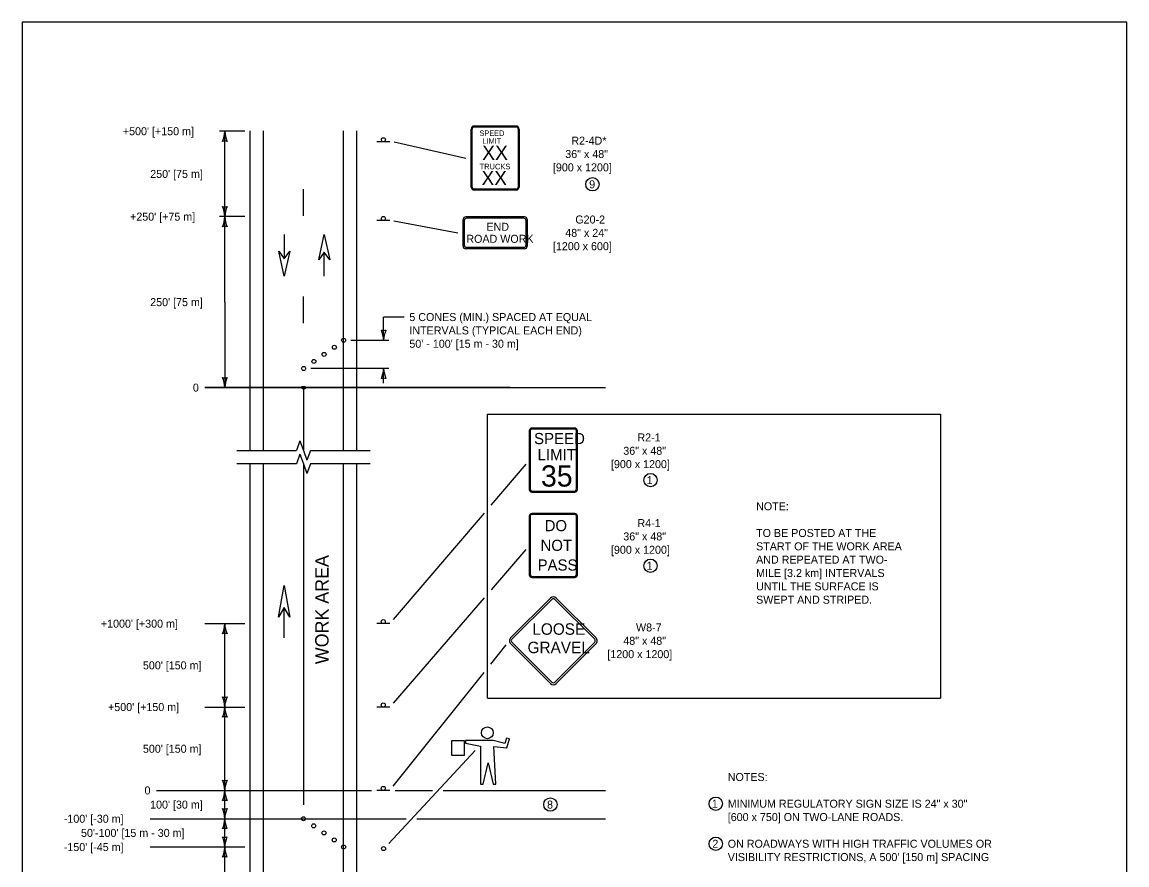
# Model space of a CAD drawing. Extents: x 49991.4 to 50021, y 49987.6 to 50011.4.
# Drawn here: x 50000.34 to 50008.61, y 50004.95 to 50011.26 of the extents above; entities that cross this region are included whole.
import ezdxf

# ---------------------------------------------------------------- set-up
doc = ezdxf.new("R2010")
doc.units = 0
for name, color, linetype in [('Level 1', 7, 'Continuous'), ('Level 2', 7, 'Continuous'), ('Level 3', 7, 'Continuous'), ('Level 6', 7, 'Continuous')]:
    doc.layers.add(name, color=color, linetype=linetype)

msp = doc.modelspace()

# ---------------------------------------------------------------- linework, layer by layer
at = {"layer": 'Level 1'}
for p, q in [((50003.7005, 50010.0267), (50003.7005, 50010.4616)), ((50003.7081, 50010.0267), (50003.7081, 50010.4616)), ((50004.038, 50010.4841), (50003.723, 50010.4841)), ((50004.038, 50010.4765), (50003.723, 50010.4765)), ((50004.0529, 50010.4616), (50004.0529, 50010.0267)), ((50004.0605, 50010.4616), (50004.0605, 50010.0267)), ((50002.0451, 50008.0525), (50002.0451, 50010.4481)), ((50002.1451, 50008.0525), (50002.1451, 50010.4481)), ((50002.745, 50008.0525), (50002.745, 50010.4481)), ((50002.845, 50008.0525), (50002.845, 50010.4481)), ((50003.0909, 50010.3657), (50002.9951, 50010.3657)), ((50003.8841, 50010.2864), (50003.8841, 50010.2864)), ((50002.445, 50009.8103), (50002.445, 50010.0102)), ((50004.038, 50010.0118), (50003.723, 50010.0118)), ((50004.038, 50010.0042), (50003.723, 50010.0042)), ((50004.1005, 50009.8033), (50003.6605, 50009.8033)), ((50003.091, 50009.7754), (50002.9951, 50009.7754)), ((50003.6405, 50009.5833), (50003.6405, 50009.7833)), ((50003.6505, 50009.5883), (50003.6505, 50009.7783)), ((50004.0955, 50009.7933), (50003.6655, 50009.7933)), ((50004.1105, 50009.7783), (50004.1105, 50009.5883)), ((50004.1205, 50009.7833), (50004.1205, 50009.5833)), ((50002.3, 50009.6701), (50002.3, 50009.4891)), ((50002.3003, 50009.6701), (50002.3003, 50009.4891)), ((50004.1004, 50009.5633), (50003.6604, 50009.5633)), ((50004.0955, 50009.5733), (50003.6655, 50009.5733)), ((50002.5997, 50009.3578), (50002.5997, 50009.5384)), ((50002.6, 50009.3578), (50002.6, 50009.5384)), ((50002.445, 50009.007), (50002.445, 50009.2068)), ((50002.4443, 50008.5236), (50002.4443, 50008.0511)), ((50004.1364, 50008.2002), (50004.1364, 50007.7602)), ((50004.1439, 50008.2002), (50004.1439, 50007.7602)), ((50004.4776, 50008.2202), (50004.1551, 50008.2202)), ((50004.4776, 50008.2122), (50004.1551, 50008.2122)), ((50004.4889, 50007.7602), (50004.4889, 50008.2002)), ((50004.4964, 50007.7602), (50004.4964, 50008.2002)), ((50002.0443, 50000.5232), (50002.0443, 50007.9525)), ((50002.1443, 50001.4605), (50002.1443, 50007.9525)), ((50002.4443, 50007.9511), (50002.4443, 50005.3976)), ((50002.7443, 50001.4605), (50002.7443, 50007.9525)), ((50002.8443, 50000.5232), (50002.8443, 50007.9525)), ((50004.1551, 50007.7482), (50004.4776, 50007.7482)), ((50004.1551, 50007.7402), (50004.4776, 50007.7402)), ((50004.4776, 50007.5806), (50004.1551, 50007.5806)), ((50004.4776, 50007.5726), (50004.1551, 50007.5726)), ((50004.1364, 50007.5606), (50004.1364, 50007.1206)), ((50004.1439, 50007.5606), (50004.1439, 50007.1206)), ((50004.4889, 50007.1206), (50004.4889, 50007.5606)), ((50004.4964, 50007.1206), (50004.4964, 50007.5606)), ((50004.1551, 50007.1086), (50004.4776, 50007.1086)), ((50004.1551, 50007.1006), (50004.4776, 50007.1006)), ((50003.9961, 50006.6476), (50004.295, 50006.9464)), ((50004.3051, 50006.9363), (50004.0062, 50006.6375)), ((50004.3051, 50006.9363), (50004.3051, 50006.9363)), ((50004.6264, 50006.6375), (50004.3276, 50006.9363)), ((50004.3377, 50006.9464), (50004.6365, 50006.6476)), ((50002.299, 50006.6496), (50002.299, 50006.8755)), ((50002.2993, 50006.6496), (50002.2993, 50006.8755)), ((50003.0903, 50006.7547), (50002.9943, 50006.7547)), ((50004.295, 50006.306), (50003.9961, 50006.6049)), ((50004.0062, 50006.615), (50004.3051, 50006.3161)), ((50004.3276, 50006.3161), (50004.6264, 50006.615)), ((50004.6365, 50006.6049), (50004.3377, 50006.306)), ((50003.0903, 50006.1297), (50002.9943, 50006.1297)), ((50003.5567, 50005.766), (50003.5567, 50005.8785)), ((50003.5567, 50005.8785), (50003.6486, 50005.8785)), ((50003.6486, 50005.8785), (50003.6486, 50005.766)), ((50003.8658, 50005.8778), (50003.6589, 50005.8778)), ((50003.6589, 50005.8778), (50003.6589, 50005.8592)), ((50003.6589, 50005.8592), (50003.7714, 50005.837)), ((50003.7714, 50005.837), (50003.7714, 50005.5507)), ((50003.9526, 50005.8578), (50003.8658, 50005.8778)), ((50003.8845, 50005.5507), (50003.8697, 50005.8341)), ((50003.8697, 50005.8341), (50003.9673, 50005.8231)), ((50003.9653, 50005.8974), (50003.9526, 50005.8578)), ((50003.9873, 50005.8919), (50003.9653, 50005.8974)), ((50003.9673, 50005.8231), (50003.9873, 50005.8919)), ((50003.6486, 50005.766), (50003.5567, 50005.766)), ((50003.7896, 50005.5507), (50003.8279, 50005.712)), ((50003.8279, 50005.712), (50003.8662, 50005.5507)), ((50003.0903, 50005.5047), (50002.9943, 50005.5047)), ((50003.7714, 50005.5507), (50003.7896, 50005.5507)), ((50003.8662, 50005.5507), (50003.8845, 50005.5507))]:
    msp.add_line(p, q, dxfattribs=at)
for points in [[(50008.6146, 50011.2628), (50000.3356, 50011.2628), (50000.3356, 50000.0624), (50008.6146, 50000.0624)], [(50002.558, 50009.4807), (50002.5997, 50009.6698), (50002.6416, 50009.4807), (50002.5997, 50009.5384)], [(50002.3421, 50009.5472), (50002.3003, 50009.3578), (50002.2585, 50009.5472), (50002.3003, 50009.4893)], [(50002.2573, 50006.8032), (50002.299, 50007.0397), (50002.3409, 50006.8032), (50002.299, 50006.8754)]]:
    msp.add_lwpolyline(points, close=True, dxfattribs=at)
for points in [[(50003.9652, 50005.8972), (50003.9654, 50005.8974)], [(50003.9667, 50005.8232), (50003.9676, 50005.8243)], [(50003.6482, 50005.766), (50003.6486, 50005.7664)]]:
    msp.add_lwpolyline(points, dxfattribs=at)
for centre, radius in [((50003.0429, 50010.3811), 0.0152), ((50003.043, 50009.7908), 0.0152), ((50002.745, 50008.8789), 0.015), ((50002.6755, 50008.8259), 0.015), ((50002.5219, 50008.7198), 0.015), ((50002.5987, 50008.7729), 0.015), ((50002.4451, 50008.6668), 0.015), ((50003.0423, 50006.7701), 0.0152), ((50003.0423, 50006.145), 0.0152), ((50003.8221, 50005.9366), 0.0442), ((50003.0423, 50005.52), 0.0152), ((50002.4442, 50005.2926), 0.015), ((50002.5211, 50005.2396), 0.015), ((50002.5979, 50005.1865), 0.015), ((50002.6747, 50005.1335), 0.015), ((50002.7442, 50005.0805), 0.015), ((50003.0442, 50005.0691), 0.0152)]:
    msp.add_circle(centre, radius, dxfattribs=at)
for centre, radius, start, end in [((50003.723, 50010.4616), 0.0225, 90, 180), ((50003.723, 50010.4616), 0.0149, 90, 180), ((50004.038, 50010.4616), 0.0225, 0, 90), ((50004.038, 50010.4616), 0.0149, 0, 90), ((50003.723, 50010.0267), 0.0225, 180, 270), ((50003.723, 50010.0267), 0.0149, 180, 270), ((50004.038, 50010.0267), 0.0225, 270, 0), ((50004.038, 50010.0267), 0.0149, 270, 0), ((50003.6605, 50009.7833), 0.02, 90, 180), ((50004.1005, 50009.7833), 0.02, 360, 90), ((50003.6655, 50009.7783), 0.015, 90, 180), ((50004.0955, 50009.7783), 0.015, 360, 90), ((50003.6604, 50009.5833), 0.02, 180, 270), ((50003.6655, 50009.5883), 0.015, 180, 270), ((50004.0955, 50009.5883), 0.015, 270, 360), ((50004.1004, 50009.5833), 0.02, 270, 360), ((50004.3164, 50006.925), 0.0302, 45.00008, 134.99993), ((50004.3164, 50006.925), 0.0159, 45.00008, 134.99993), ((50004.0175, 50006.6262), 0.0302, 134.99993, 225.00008), ((50004.0175, 50006.6262), 0.0159, 134.99993, 225.00008), ((50004.6152, 50006.6262), 0.0159, 314.99993, 45.00007), ((50004.6152, 50006.6262), 0.0302, 314.99993, 45.00008), ((50004.3164, 50006.3273), 0.0302, 225.00007, 314.99993), ((50004.3164, 50006.3273), 0.0159, 225.00007, 314.99993)]:
    msp.add_arc(centre, radius, start, end, dxfattribs=at)
msp.add_ellipse((50002.4451, 50008.5236), major_axis=(-0.015, 0), ratio=0.8, dxfattribs=at)
for centre, major_axis, start_param, end_param in [((50004.1552, 50008.2002), (0, 0.02), 0, 1.570796), ((50004.1552, 50008.2002), (0, 0.012), 0, 1.570796), ((50004.4777, 50008.2002), (0, 0.02), 4.712389, 6.283185), ((50004.4777, 50008.2002), (0, 0.012), 4.712389, 6.283185), ((50004.1552, 50007.7602), (0, -0.02), 4.712389, 6.283185), ((50004.1552, 50007.7602), (0, -0.012), 4.712389, 6.283185), ((50004.4777, 50007.7602), (0, -0.02), 0, 1.570796), ((50004.4777, 50007.7602), (0, -0.012), 0, 1.570796), ((50004.1552, 50007.5605), (0, 0.02), 0, 1.570796), ((50004.1552, 50007.5605), (0, 0.012), 0, 1.570796), ((50004.4777, 50007.5605), (0, 0.02), 4.712389, 6.283185), ((50004.4777, 50007.5605), (0, 0.012), 4.712389, 6.283185), ((50004.1552, 50007.1205), (0, -0.02), 4.712389, 6.283185), ((50004.1552, 50007.1205), (0, -0.012), 4.712389, 6.283185), ((50004.4777, 50007.1205), (0, -0.02), 0, 1.570796), ((50004.4777, 50007.1205), (0, -0.012), 0, 1.570796)]:
    msp.add_ellipse(centre, major_axis=major_axis, ratio=0.9375, start_param=start_param, end_param=end_param, dxfattribs=at)
at = {"layer": 'Level 2'}
for p, q in [((50003.8232, 50008.3236), (50007.2172, 50008.3236)), ((50003.8232, 50006.1967), (50003.8232, 50008.3236)), ((50007.2172, 50008.3236), (50007.2172, 50006.1967)), ((50003.8232, 50006.1967), (50007.2172, 50006.1967))]:
    msp.add_line(p, q, dxfattribs=at)
for centre in [(50004.6097, 50010.0473), (50005.0447, 50007.8302), (50005.0445, 50007.1884), (50004.2943, 50005.3987), (50005.5336, 50005.4053), (50005.5336, 50005.1053)]:
    msp.add_circle(centre, 0.05, dxfattribs=at)
at = {"layer": 'Level 3'}
for p, q in [((50002.005, 50010.4452), (50001.8151, 50010.4452)), ((50001.8551, 50009.8047), (50001.8551, 50010.4452)), ((50003.1241, 50010.3657), (50003.6605, 50010.2442)), ((50002.0051, 50009.8047), (50001.8151, 50009.8047)), ((50002.0051, 50009.8047), (50001.8151, 50009.8047)), ((50001.8551, 50009.1641), (50001.8551, 50009.8047)), ((50003.1221, 50009.7727), (50003.6005, 50009.6833)), ((50001.8551, 50009.1641), (50001.8551, 50008.5236)), ((50003.045, 50008.8789), (50003.045, 50009.0523)), ((50003.1976, 50009.0523), (50003.045, 50009.0523)), ((50002.8, 50008.8789), (50003.085, 50008.8789)), ((50003.085, 50008.6668), (50002.5001, 50008.6668)), ((50003.045, 50008.5576), (50003.045, 50008.6668)), ((50003.9937, 50008.5236), (50001.7043, 50008.5236)), ((50001.7051, 50008.5236), (50004.7081, 50008.5236)), ((50004.1104, 50007.9498), (50003.8492, 50007.6437)), ((50003.7972, 50007.5829), (50003.1163, 50006.7851)), ((50004.1103, 50007.3103), (50003.8494, 50007.0083)), ((50003.7971, 50006.9478), (50003.1164, 50006.16)), ((50001.7043, 50006.7547), (50002.0043, 50006.7547)), ((50001.8543, 50006.1297), (50001.8543, 50006.7547)), ((50003.8482, 50006.4522), (50003.9623, 50006.5949)), ((50003.1153, 50005.5359), (50003.7982, 50006.3897)), ((50001.7043, 50006.1297), (50002.0043, 50006.1297)), ((50001.8543, 50005.5047), (50001.8543, 50006.1297)), ((50003.7314, 50005.8049), (50003.083, 50005.1083)), ((50001.3418, 50005.5047), (50002.9543, 50005.5047)), ((50001.8543, 50005.2926), (50001.8543, 50005.5047)), ((50003.1303, 50005.5047), (50003.4119, 50005.5047)), ((50003.4919, 50005.5047), (50004.7073, 50005.5047)), ((50001.2962, 50005.2926), (50003.2145, 50005.2926)), ((50001.8542, 50005.0805), (50001.8542, 50005.2926)), ((50003.2945, 50005.2926), (50004.7073, 50005.2926)), ((50002.0043, 50005.0805), (50001.2962, 50005.0805)), ((50001.8543, 50004.8684), (50001.8542, 50005.0805))]:
    msp.add_line(p, q, dxfattribs=at)
for centre, radius, start, end in [((50001.6329, 50010.4543), 0.2223, 337.45601, 357.63952), ((50002.0878, 50010.4567), 0.233, 182.82731, 202.07716), ((50001.8551, 50010.317), 0.0548, 72.13882, 107.86118), ((50001.8551, 50009.9329), 0.0548, 252.13882, 287.86118), ((50001.6224, 50009.7932), 0.233, 2.82731, 22.07716), ((50002.0772, 50009.7955), 0.2223, 157.45601, 177.63952), ((50001.633, 50009.8138), 0.2223, 337.45601, 357.63952), ((50002.0878, 50009.8162), 0.233, 182.82731, 202.07716), ((50001.8551, 50009.6764), 0.0548, 72.13882, 107.86118), ((50003.045, 50009.0071), 0.0548, 252.13882, 287.86118), ((50002.8123, 50008.8674), 0.233, 2.82731, 22.07716), ((50003.2671, 50008.8698), 0.2223, 157.45601, 177.63952), ((50002.8229, 50008.676), 0.2223, 337.45601, 357.63952), ((50003.2777, 50008.6783), 0.233, 182.82731, 202.07716), ((50001.8551, 50008.6518), 0.0548, 252.13882, 287.86118), ((50001.6224, 50008.5121), 0.233, 2.82731, 22.07716), ((50002.0773, 50008.5145), 0.2223, 157.45601, 177.63952), ((50003.045, 50008.5386), 0.0548, 72.13882, 107.86118), ((50001.6322, 50006.7639), 0.2223, 337.45601, 357.63952), ((50002.087, 50006.7662), 0.233, 182.82731, 202.07716), ((50001.8543, 50006.6265), 0.0548, 72.13882, 107.86118), ((50001.8543, 50006.2579), 0.0548, 252.13882, 287.86118), ((50001.6216, 50006.1182), 0.233, 2.82731, 22.07716), ((50002.0764, 50006.1205), 0.2223, 157.45601, 177.63952), ((50001.6322, 50006.1389), 0.2223, 337.45601, 357.63952), ((50002.087, 50006.1412), 0.233, 182.82731, 202.07716), ((50001.8543, 50006.0015), 0.0548, 72.13882, 107.86118), ((50001.8543, 50005.6329), 0.0548, 252.13882, 287.86118), ((50001.6216, 50005.4932), 0.233, 2.82731, 22.07716), ((50002.0764, 50005.4955), 0.2223, 157.45601, 177.63952), ((50001.6322, 50005.5139), 0.2223, 337.45601, 357.63952), ((50002.087, 50005.5162), 0.233, 182.82731, 202.07716), ((50001.8543, 50005.3765), 0.0548, 72.13882, 107.86118), ((50001.8543, 50005.4208), 0.0548, 252.13882, 287.86118), ((50001.6216, 50005.2811), 0.233, 2.82731, 22.07716), ((50002.0764, 50005.2834), 0.2223, 157.45601, 177.63952), ((50001.6321, 50005.3018), 0.2223, 337.45601, 357.63952), ((50002.0869, 50005.3041), 0.233, 182.82731, 202.07716), ((50001.8542, 50005.1644), 0.0548, 72.13882, 107.86118), ((50001.8542, 50005.2087), 0.0548, 252.13882, 287.86118), ((50001.6215, 50005.069), 0.233, 2.82731, 22.07716), ((50001.6321, 50005.0896), 0.2223, 337.45601, 357.63952), ((50002.0763, 50005.0713), 0.2223, 157.45601, 177.63952), ((50002.0869, 50005.092), 0.233, 182.82731, 202.07716), ((50001.8542, 50004.9523), 0.0548, 72.13882, 107.86118)]:
    msp.add_arc(centre, radius, start, end, dxfattribs=at)
at = {"layer": 'Level 6'}
for p, q in [((50002.4179, 50008.1256), (50002.392, 50008.0525)), ((50002.4179, 50008.1256), (50002.4438, 50008.0525)), ((50001.9451, 50008.0525), (50002.392, 50008.0525)), ((50002.4179, 50008.0256), (50002.392, 50007.9525)), ((50002.4179, 50008.0256), (50002.4438, 50007.9525)), ((50002.4438, 50008.0525), (50002.4697, 50007.9794)), ((50002.4956, 50008.0525), (50002.4697, 50007.9794)), ((50002.4956, 50008.0525), (50002.945, 50008.0525)), ((50002.392, 50007.9525), (50001.9443, 50007.9525)), ((50002.4438, 50007.9525), (50002.4697, 50007.8794)), ((50002.4956, 50007.9525), (50002.4697, 50007.8794)), ((50002.9443, 50007.9525), (50002.4956, 50007.9525))]:
    msp.add_line(p, q, dxfattribs=at)

# ---------------------------------------------------------------- texts
at = {"layer": 'Level 1'}
for s, height, p in [('SPEED', 0.04121, (50003.7628, 50010.41)), ('LIMIT', 0.04162, (50003.7846, 50010.3506)), ('XX', 0.10831, (50003.7829, 50010.2296)), ('TRUCKS', 0.04183, (50003.7644, 50010.1593)), ('XX', 0.10679, (50003.7784, 50010.0412)), ('SPEED', 0.0841, (50004.1719, 50008.0998)), ('LIMIT', 0.0841, (50004.1985, 50007.9797)), ('35', 0.15914, (50004.224, 50007.7819))]:
    msp.add_text(s, height=height, dxfattribs=at).set_placement(p)
for s, height, p in [('END', 0.06, (50003.8153, 50009.6987)), ('ROAD WORK', 0.06, (50003.6646, 50009.6087)), ('DO', 0.08352, (50004.2515, 50007.4474)), ('NOT', 0.08352, (50004.2209, 50007.2999)), ('PASS', 0.08352, (50004.1989, 50007.1524)), ('LOOSE', 0.08598, (50004.1593, 50006.6713)), ('GRAVEL', 0.08598, (50004.1233, 50006.5335))]:
    msp.add_text(s, height=height, rotation=360, dxfattribs=at).set_placement(p)
at = {"layer": 'Level 2'}
for s, height, p in [("+500' [+150 m]", 0.059993, (50001.0906, 50010.4152)), ('R2-4D*', 0.06, (50004.4514, 50010.3442)), ('36" x 48"', 0.06, (50004.4059, 50010.2442)), ("250' [75 m]", 0.059993, (50001.2957, 50010.0949)), ('[900 x 1200]', 0.06, (50004.3134, 50010.1442)), ('9', 0.06, (50004.5852, 50010.0173)), ("+250' [+75 m]", 0.059993, (50001.1445, 50009.7747)), ('G20-2', 0.05999, (50004.4811, 50009.7533)), ('48" x 24"', 0.05999, (50004.4059, 50009.6533)), ('[1200 x 600]', 0.059993, (50004.3134, 50009.5534)), ("250' [75 m]", 0.059993, (50001.2956, 50009.1341)), ('5 CONES (MIN.) SPACED AT EQUAL ', 0.06, (50003.2376, 50009.0223)), ('INTERVALS (TYPICAL EACH END)', 0.06, (50003.2376, 50008.9223)), ("50' - 100' [15 m - 30 m]", 0.06, (50003.2376, 50008.8223)), ('0', 0.06, (50001.6155, 50008.4936)), ('R2-1', 0.06, (50004.9464, 50008.1202)), ('36" x 48"', 0.06, (50004.8408, 50008.0202)), ('[900 x 1200]', 0.06, (50004.7483, 50007.9202)), ('1', 0.06, (50005.0159, 50007.8002)), ('NOTE:', 0.06, (50005.8359, 50007.6042)), ('R4-1', 0.06, (50004.9464, 50007.4784)), ('36" x 48"', 0.06, (50004.8408, 50007.3784)), ('TO BE POSTED AT THE', 0.06, (50005.8359, 50007.4042)), ('[900 x 1200]', 0.06, (50004.7483, 50007.2784)), ('START OF THE WORK AREA', 0.06, (50005.8359, 50007.3042)), ('AND REPEATED AT TWO-', 0.06, (50005.8359, 50007.2042)), ('1', 0.06, (50005.0156, 50007.1588)), ('MILE [3.2 km] INTERVALS', 0.06, (50005.8359, 50007.1042)), ('UNTIL THE SURFACE IS', 0.06, (50005.8359, 50007.0042)), ('SWEPT AND STRIPED.', 0.06, (50005.8359, 50006.9042)), ("+1000' [+300 m]", 0.06, (50000.9258, 50006.7247)), ('W8-7', 0.06, (50004.936, 50006.6962)), ('48" x 48"', 0.06, (50004.8408, 50006.5962)), ('[1200 x 1200]', 0.06, (50004.7214, 50006.4962)), ("500' [150 m]", 0.06, (50001.2409, 50006.4122)), ("+500' [+150 m]", 0.06, (50000.9797, 50006.0997)), ("500' [150 m]", 0.06, (50001.2409, 50005.7872)), ('NOTES:', 0.06, (50005.6236, 50005.5753)), ('0', 0.06, (50001.253, 50005.4747)), ("100' [30 m]", 0.06, (50001.2948, 50005.3686)), ('8', 0.06, (50004.2693, 50005.3687)), ('1', 0.06, (50005.5042, 50005.3753)), ('MINIMUM REGULATORY SIGN SIZE IS 24" x 30"', 0.06, (50005.6236, 50005.3753)), ("-100' [-30 m]", 0.06, (50000.6482, 50005.2626)), ('[600 x 750] ON TWO-LANE ROADS.', 0.06, (50005.6236, 50005.2753)), ("50'-100' [15 m - 30 m]", 0.06, (50000.7772, 50005.1565)), ("-150' [-45 m]", 0.06, (50000.6482, 50005.0505)), ('2', 0.06, (50005.5084, 50005.0753)), ('ON ROADWAYS WITH HIGH TRAFFIC VOLUMES OR', 0.06, (50005.6236, 50005.0753)), ("VISIBILITY RESTRICTIONS, A 500' [150 m] SPACING ", 0.06, (50005.6236, 50004.9753))]:
    msp.add_text(s, height=height, dxfattribs=at).set_placement(p)
msp.add_text('WORK AREA', height=0.1, rotation=90, dxfattribs=at).set_placement((50002.6319, 50006.451))

doc.saveas('drawing.dxf')
